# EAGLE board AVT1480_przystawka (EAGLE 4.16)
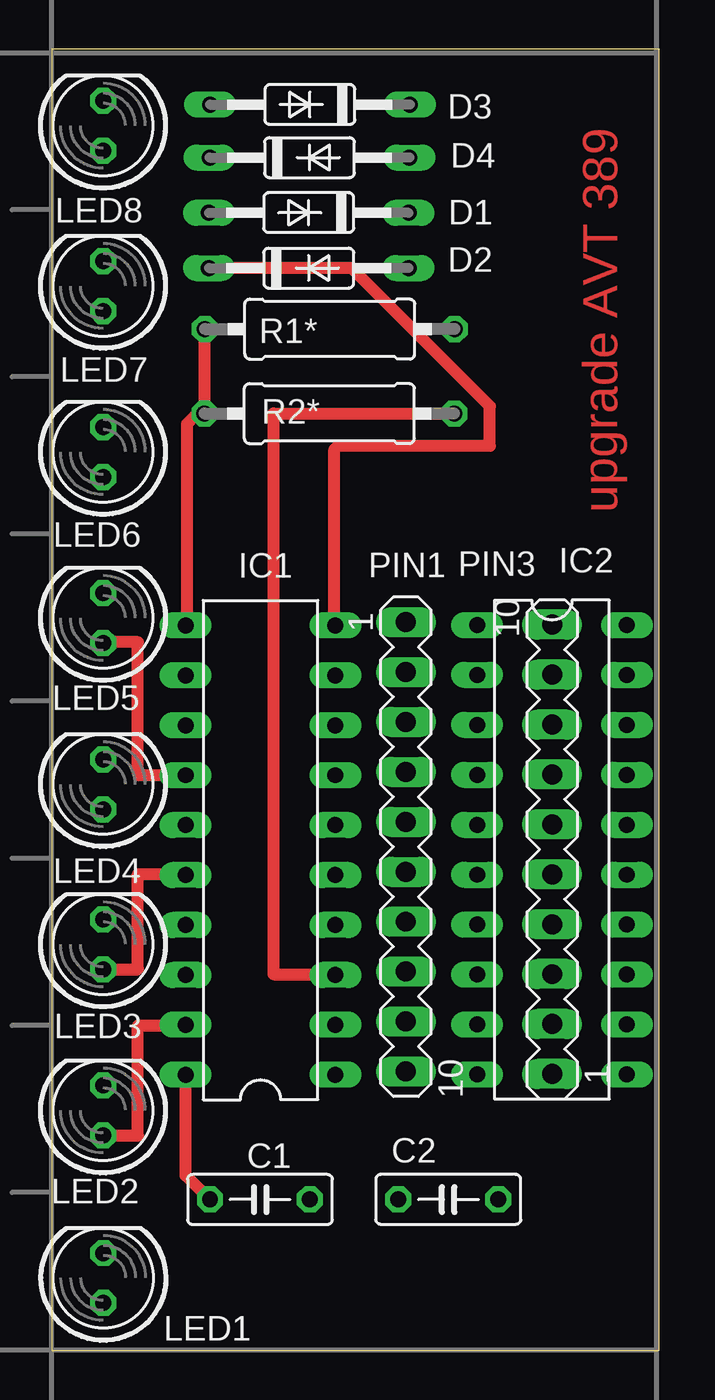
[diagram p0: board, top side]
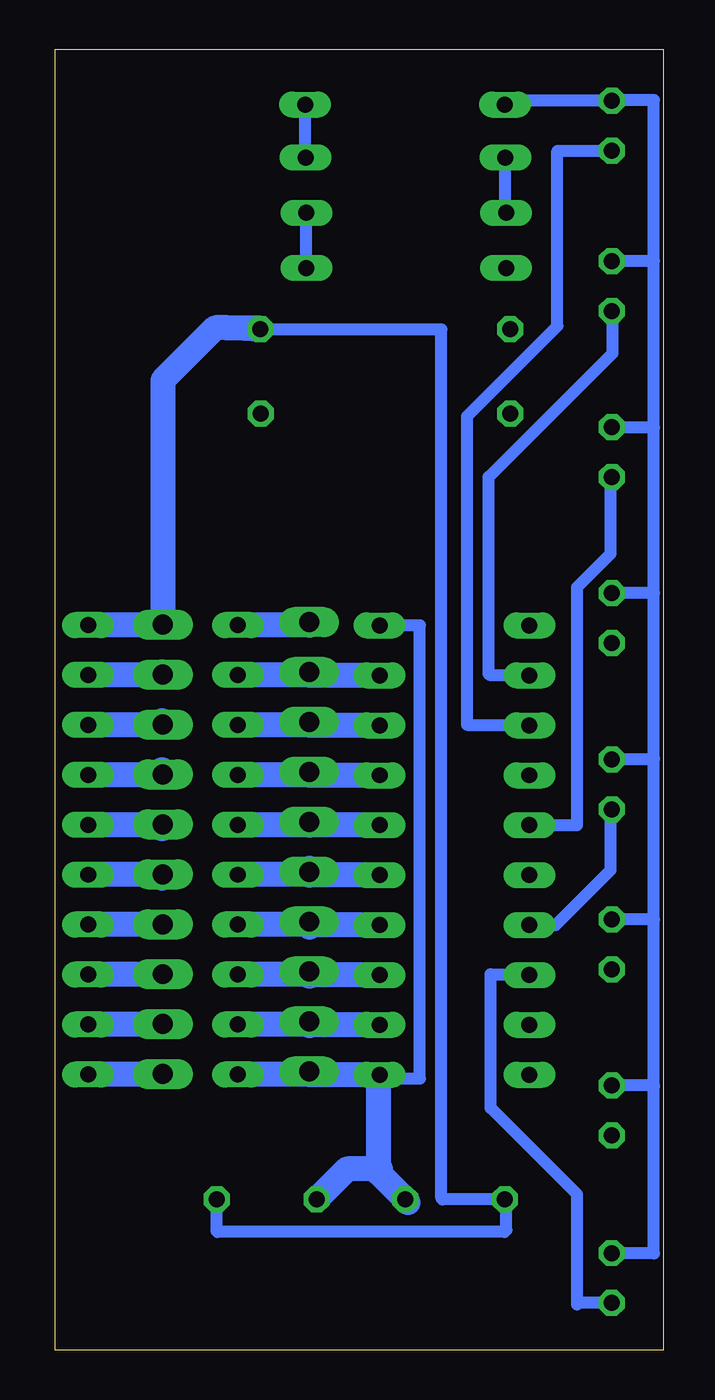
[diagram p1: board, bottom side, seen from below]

Size 30.9 x 66.2 mm. Coordinates in mm from the lower left corner, seen from the top.
Outline: 0,0 30.9,0 30.9,66.2 0,66.2 0,0
Copper layers (1*16): Top 0.035mm / dielectric 1.5mm / Bottom 0.035mm
Design rules "default": minimum track width 20mil, minimum drill 24mil, track to track 8mil, track to pad 8mil, pad to pad 8mil, via to via 8mil, smd to smd 8mil, copper to edge 40mil, drill to drill 8mil, minimum pad ring 10mil, minimum via ring 8mil, stop-mask expansion 4mil, vias tented up to drill 0mil, thermal gap 10mil

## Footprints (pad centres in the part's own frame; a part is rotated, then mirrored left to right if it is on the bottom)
C050-025X075 = drill 0.813 octagon: 1 -2.54,0; 2 2.54,0
DO35-10 = drill 0.813 long: A 5.08,0; C -5.08,0
DIL20 = drill 0.813 long: 1 -11.43,-3.81; 2 -8.89,-3.81; 3 -6.35,-3.81; 4 -3.81,-3.81; 5 -1.27,-3.81; 6 1.27,-3.81; 7 3.81,-3.81; 8 6.35,-3.81; 9 8.89,-3.81; 10 11.43,-3.81; 11 11.43,3.81; 12 8.89,3.81; 13 6.35,3.81; 14 3.81,3.81; 15 1.27,3.81; 16 -1.27,3.81; 17 -3.81,3.81; 18 -6.35,3.81; 19 -8.89,3.81; 20 -11.43,3.81
LED5MM = drill 0.813 octagon: A -1.27,0; K 1.27,0
MA10-1 = drill 1.016 long: 1 -11.43,0; 2 -8.89,0; 3 -6.35,0; 4 -3.81,0; 5 -1.27,0; 6 1.27,0; 7 3.81,0; 8 6.35,0; 9 8.89,0; 10 11.43,0
0309/12 = drill 0.813 octagon: 1 -6.35,0; 2 6.35,0

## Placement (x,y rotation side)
C1  100n  [C050-025X075]  10.58,7.68 0 top
C2  100n  [C050-025X075]  20.16,7.68 180 top
D1  [DO35-10]  13.06,55.06 0 top
D2  [DO35-10]  13.06,57.88 180 top
D3  [DO35-10]  13.1,60.68 0 top
D4  [DO35-10]  13.12,63.38 180 top
IC1  74HCT573N  [DIL20]  10.61,25.45 90 top
IC2  74HCT573N  [DIL20]  25.43,25.47 270 top
LED1  [LED5MM]  2.62,3.68 90 top
LED2  [LED5MM]  2.6,12.2 90 top
LED3  [LED5MM]  2.6,20.65 90 top
LED4  [LED5MM]  2.6,28.8 90 top
LED5  [LED5MM]  2.6,37.25 90 top
LED6  [LED5MM]  2.6,45.7 90 top
LED7  [LED5MM]  2.6,54.15 90 top
LED8  [LED5MM]  2.6,62.3 90 top
PIN1  [MA10-1]  18,25.62 270 top
PIN3  [MA10-1]  25.44,25.49 90 top
R1*  10k  [0309/12]  14.13,51.96 0 top
R2*  1k  [0309/12]  14.11,47.66 0 top

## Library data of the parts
C1 C2 R1* R2* = rcl
D1-D4 = diode
IC1 IC2 = 74xx-eu
LED1-LED8 = led
PIN1 PIN3 = con-lstb

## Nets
1: IC2.1 PIN1.1
2: IC1.9 IC2.2 PIN1.2
3: IC1.8 IC2.3 PIN1.3
4: IC1.7 IC2.4 PIN1.4
5: IC1.6 IC2.5 PIN1.5
6: IC1.5 IC2.6 PIN1.6
7: IC1.4 IC2.7 PIN1.7
8: IC1.3 IC2.8 PIN1.8 R2*.2
9: IC1.2 IC2.9 PIN1.9
11: IC2.11 PIN3.1
GND: C1.2 C2.2 D1.C IC1.1 IC1.10 IC2.10 PIN1.10
N$1: IC1.12 LED7.A
N$2: IC1.13 LED8.A
N$3: IC1.14 LED5.A
N$4: IC1.15 LED6.A
N$5: IC1.16 LED3.A
N$6: IC1.17 LED4.A
N$7: IC1.18 LED1.A
N$8: IC1.19 LED2.A
N$9: D4.A LED1.K LED2.K LED3.K LED4.K LED5.K LED6.K LED7.K LED8.K
N$10: D3.A D4.C
N$11: D2.A D3.C
N$12: D1.A D2.C
N$15: IC2.19 PIN3.9
N$16: IC2.18 PIN3.8
N$17: IC2.17 PIN3.7
N$18: IC2.16 PIN3.6
N$19: IC2.15 PIN3.5
N$20: IC2.14 PIN3.4
N$21: IC2.13 PIN3.3
N$22: IC2.12 PIN3.2
N$23: IC1.11 R1*.1 R2*.1
VCC: C1.1 C2.1 IC1.20 IC2.20 PIN3.10 R1*.2

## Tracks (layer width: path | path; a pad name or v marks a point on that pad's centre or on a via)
1
  Bottom 1.27: PIN1.1 17.97,37.05 17.97,36.9 IC2.1
2
  Bottom 1.27: IC2.2 17.97,34.36 17.97,34.51 | 17.97,34.51 17.97,34.53 | 17.97,34.51 PIN1.2 | IC1.9 17.97,34.34 17.97,34.51
3
  Bottom 1.27: IC2.3 17.97,31.82 17.97,31.97 | 17.97,31.97 17.97,32.03 | 17.97,31.97 PIN1.3 | IC1.8 17.97,31.8 17.97,31.97
4
  Bottom 1.27: IC2.4 17.97,29.28 17.97,29.43 | 17.97,29.43 17.97,29.53 | 17.97,29.43 PIN1.4 | IC1.7 17.97,29.26 17.97,29.43
5
  Bottom 1.27: IC2.5 17.97,26.74 17.97,26.89 | 17.97,26.89 17.97,27.03 | 17.97,26.89 PIN1.5 | IC1.6 17.97,26.72 17.97,26.89
6
  Bottom 1.27: IC2.6 17.97,24.2 17.97,24.35 | 17.97,24.35 17.97,24.53 | 17.97,24.35 PIN1.6 | IC1.5 17.97,24.18 17.97,24.35
7
  Bottom 1.27: 17.97,21.66 IC2.7 | 17.97,21.64 17.97,21.66 | 17.97,21.66 17.97,21.81 PIN1.7 | IC1.4 17.97,21.64 | 17.97,21.64 17.97,21.53
8
  Top 0.61: R2*.2 11.27,47.66 11.27,19.13 14.47,19.13 14.47,19.1 | 14.47,19.1 14.47,19.03 | 14.47,19.1 IC1.3
  Bottom 1.27: 17.97,19.12 IC2.8 | 17.97,19.1 17.97,19.12 | 17.97,19.12 17.97,19.27 PIN1.8 | IC1.3 17.97,19.1 | 17.97,19.1 17.97,19.03
9
  Bottom 1.27: 17.97,16.58 IC2.9 | 17.97,16.56 17.97,16.58 | 17.97,16.58 17.97,16.73 PIN1.9 | IC1.2 17.97,16.56 | 17.97,16.56 17.97,16.53
11
  Bottom 1.27: 25.47,14.04 25.47,14.06 PIN3.1 | 25.47,14.04 IC2.11 | 25.47,14.04 25.47,14.03
GND
  Top 0.61: D1.C 15.24,55.06 22.27,48.03 22.27,46.03 14.57,46.03 14.37,45.83 14.37,36.83 | IC1.10 14.37,36.83 | 14.37,36.83 14.27,36.73
  Bottom 0.61: IC1.10 12.37,36.88 12.37,13.83 14.57,13.83 14.57,14.02 IC1.1
  Bottom 1.27: 17.97,14.04 IC2.10 | 17.97,14.04 17.97,14.19 PIN1.10 | 17.97,14.04 17.97,14.02 IC1.1 14.47,14.02 14.47,9.23 | 14.47,9.23 14.47,9.03 C1.2 12.97,7.53 | 14.47,9.23 14.37,9.23 | C2.2 16.07,9.23 14.47,9.23
N$1
  Bottom 0.61: IC1.12 8.78,34.34 8.87,34.43 8.87,44.43 2.57,50.73 2.57,52.93 2.6,52.9 LED7.A
N$2
  Bottom 0.61: IC1.13 9.9,31.8 9.97,31.83 9.97,47.53 5.47,52.03 | 5.37,52.13 5.37,61.03 LED8.A
N$3
  Top 0.61: IC1.14 4.44,29.26 4.37,29.33 4.37,36.03 2.57,36.03 2.6,36 LED5.A
N$4
  Bottom 0.61: IC1.15 4.38,26.72 4.37,26.73 4.37,38.83 2.67,40.53 2.67,44.33 2.57,44.43 LED6.A
N$5
  Top 0.61: LED3.A 4.32,19.38 4.37,19.43 4.37,24.23 6.77,24.23 6.82,24.18 | 6.87,24.13 6.82,24.18 | 6.82,24.18 IC1.16
N$6
  Bottom 0.61: IC1.17 5.46,21.64 2.67,24.43 2.67,27.43 2.57,27.53 LED4.A
N$7
  Bottom 0.61: LED1.A 4.29,2.41 4.37,2.33 4.37,7.93 8.77,12.33 8.77,19.13 6.87,19.13 6.84,19.1 IC1.18
N$8
  Top 0.61: LED2.A 4.37,10.93 4.37,16.53 6.87,16.53 6.87,16.56 IC1.19
N$9
  Bottom 0.61: 0.47,46.93 0.47,55.43 | 0.47,55.43 0.47,63.61 2.57,63.61 2.57,63.57 | 0.47,38.53 0.47,46.93 | 0.47,30.13 0.47,38.53 | 0.47,21.93 0.47,30.13 | 0.47,4.95 0.47,13.43 | 0.47,13.43 0.47,21.93 | 2.57,63.57 2.57,63.53 | 2.57,63.57 LED8.K 8.07,63.57 8.07,63.38 | 8.07,63.38 8.07,63.33 | 8.07,63.38 D4.A | LED7.K 0.47,55.42 0.47,55.43 | 0.47,4.95 LED1.K | 0.47,4.93 0.47,4.95 | LED2.K 0.47,13.47 0.47,13.43 | LED3.K 0.47,21.92 0.47,21.93 | LED4.K 0.47,30.07 0.47,30.13 | LED5.K 0.47,38.52 0.47,38.53 | LED6.K 0.47,46.97 0.47,46.93
N$10
  Bottom 0.61: 18.18,60.64 18.17,60.63 | D3.A 18.18,60.64 | D4.C 18.2,60.66 18.18,60.64
N$11
  Bottom 0.61: 7.98,57.84 7.97,57.83 | D2.A 7.98,57.84 | D3.C 8.02,57.88 7.98,57.84
N$12
  Bottom 0.61: D2.C D1.A 18.17,55.03
N$15
  Bottom 1.27: 25.47,34.38 25.47,34.53 | PIN3.9 25.47,34.38 | IC2.19 25.47,34.36 25.47,34.38
N$16
  Bottom 1.27: 25.47,31.84 25.47,32.03 | PIN3.8 25.47,31.84 | IC2.18 25.47,31.82 25.47,31.84
N$17
  Bottom 1.27: 25.47,29.3 25.47,29.53 | PIN3.7 25.47,29.3 | IC2.17 25.47,29.28 25.47,29.3
N$18
  Bottom 1.27: 25.47,26.74 25.47,26.76 PIN3.6 | 25.47,26.74 IC2.16 | 25.47,26.74 25.47,26.53
N$19
  Bottom 1.27: 25.47,24.2 25.47,24.22 PIN3.5 | 25.47,24.2 IC2.15 | 25.47,24.2 25.47,24.03
N$20
  Bottom 1.27: 25.47,21.66 25.47,21.68 PIN3.4 | 25.47,21.66 IC2.14 | 25.47,21.66 25.47,21.53
N$21
  Bottom 1.27: 25.47,19.12 25.47,19.14 PIN3.3 | 25.47,19.12 IC2.13 | 25.47,19.12 25.47,19.03
N$22
  Bottom 1.27: 25.47,16.58 25.47,16.6 PIN3.2 | 25.47,16.58 IC2.12 | 25.47,16.58 25.47,16.53
N$23
  Top 0.61: R1*.1 7.78,47.54 7.77,47.53 7.76,47.54 R2*.1 7.4,47.66 6.87,47.13 6.87,36.93 6.8,36.86 | 6.77,36.83 6.8,36.86 | 6.8,36.86 IC1.11
VCC
  Top 0.61: C1.1 8.02,7.68 6.8,8.9 IC1.20
  Bottom 0.61: 20.48,51.92 20.57,51.83 | 20.48,51.92 R1*.2 | 20.48,51.92 20.47,51.93 11.27,51.93 11.27,7.73 11.22,7.68 C1.1 8.02,7.68 7.97,7.63 7.97,6.13 8.07,6.03 22.67,6.03 22.7,6.06 C2.1
  Bottom 1.27: 25.47,36.92 25.47,37.03 | 25.47,36.92 PIN3.10 25.44,49.36 22.77,52.03 22.17,52.03 | IC2.20 25.47,36.9 25.47,36.92 | 20.48,51.94 22.17,52.03 | R1*.2 20.48,51.94 | 22.17,52.03 20.57,52.03 20.48,51.94

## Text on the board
Top: upgrade AVT 389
